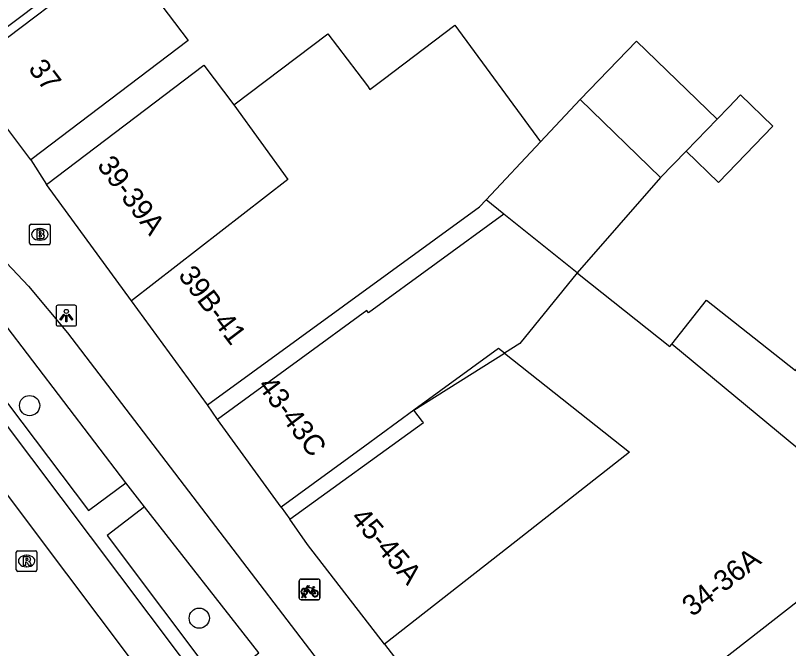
# Model space of a CAD drawing. Extents: x 161882 to 162509, y 381687 to 382379.
# Drawn here: x 162023.23 to 162060.59, y 382035.63 to 382066.22 of the extents above; entities that cross this region are included whole.
import ezdxf

# ---------------------------------------------------------------- set-up
doc = ezdxf.new("R2010")
doc.units = 0
for name, color, linetype in [('IMGEO_Boom', 7, 'Continuous'), ('IMGEO_Brandkraan', 7, 'Continuous'), ('IMGEO_Fietsenrek', 7, 'Continuous'), ('IMGEO_Fietspad_gesloten', 7, 'Continuous'), ('IMGEO_Lichtpunt', 7, 'Continuous'), ('IMGEO_Pand', 7, 'Continuous'), ('IMGEO_Pand_nummerreeks', 7, 'Continuous'), ('IMGEO_Rijbaan_lokaal_gesloten', 7, 'Continuous'), ('IMGEO_Rioolput', 7, 'Continuous'), ('IMGEO_Voetpad_open', 7, 'Continuous')]:
    doc.layers.add(name, color=color, linetype=linetype)

msp = doc.modelspace()

# ---------------------------------------------------------------- linework, layer by layer
at = {"layer": 'IMGEO_Boom'}
for centre in [(162023.912, 382047.368), (162032.11, 382037.095)]:
    msp.add_circle(centre, 0.489, dxfattribs=at)
at = {"layer": 'IMGEO_Brandkraan'}
for p, q in [((162023.908, 382055.218), (162023.908, 382056.07)), ((162023.983, 382056.144), (162024.835, 382056.144)), ((162024.909, 382056.07), (162024.909, 382055.218)), ((162024.396, 382055.924), (162024.421, 382055.924)), ((162024.419, 382055.364), (162024.394, 382055.364)), ((162024.835, 382055.144), (162023.983, 382055.144))]:
    msp.add_line(p, q, dxfattribs=at)
for points in [[(162023.908, 382055.218), (162023.908, 382056.07)], [(162023.983, 382056.144), (162024.835, 382056.144)], [(162024.909, 382056.07), (162024.909, 382055.218)], [(162024.256, 382055.844), (162024.256, 382055.444), (162024.469, 382055.444)], [(162024.487, 382055.844), (162024.256, 382055.844)], [(162024.435, 382055.763), (162024.381, 382055.763), (162024.381, 382055.687)], [(162024.381, 382055.687), (162024.434, 382055.687)], [(162024.443, 382055.611), (162024.381, 382055.611), (162024.381, 382055.53)], [(162024.381, 382055.53), (162024.443, 382055.53)], [(162024.835, 382055.144), (162023.983, 382055.144)]]:
    msp.add_lwpolyline(points, dxfattribs=at)
for centre, radius, start, end in [((162023.985, 382056.068), 0.0765, 91.552, 178.448), ((162023.985, 382056.068), 0.0765, 91.552, 178.448), ((162024.833, 382056.068), 0.0765, 1.552, 88.448), ((162024.833, 382056.068), 0.0765, 1.552, 88.448), ((162024.436, 382055.725), 0.0379, 267.8285, 90.9355), ((162024.444, 382055.57), 0.0404, 269.8759, 90.5077), ((162024.491, 382055.699), 0.145, 59.4692, 91.5367), ((162024.516, 382055.746), 0.0922, 285.5137, 58.1501), ((162024.521, 382055.554), 0.105, 301.3115, 78.989), ((162023.985, 382055.22), 0.0765, 181.552, 268.448), ((162023.985, 382055.22), 0.0765, 181.552, 268.448), ((162024.475, 382055.695), 0.251, 268.6676, 293.5347), ((162024.833, 382055.22), 0.0765, 271.552, 358.448), ((162024.833, 382055.22), 0.0765, 271.552, 358.448)]:
    msp.add_arc(centre, radius, start, end, dxfattribs=at)
for centre, major_axis, ratio, start_param, end_param in [((162024.395, 382055.644), (-0.387, 0.002), 0.722429, 4.712389, 7.853982), ((162024.42, 382055.644), (-0.39, 0.002), 0.717154, 1.570796, 4.712389)]:
    msp.add_ellipse(centre, major_axis=major_axis, ratio=ratio, start_param=start_param, end_param=end_param, dxfattribs=at)
at = {"layer": 'IMGEO_Fietsenrek'}
for p, q in [((162036.945, 382038.062), (162036.945, 382038.903)), ((162036.945, 382038.903), (162036.945, 382038.062)), ((162037.02, 382038.987), (162037.861, 382038.987)), ((162037.861, 382038.987), (162037.02, 382038.987)), ((162037.945, 382038.912), (162037.945, 382038.071)), ((162037.945, 382038.071), (162037.945, 382038.912)), ((162037.632, 382038.536), (162037.668, 382038.441)), ((162037.072, 382038.071), (162037.111, 382038.231)), ((162037.106, 382038.071), (162037.072, 382038.071)), ((162037.141, 382038.219), (162037.106, 382038.071)), ((162037.183, 382038.243), (162037.182, 382038.247)), ((162037.224, 382038.071), (162037.19, 382038.213)), ((162037.214, 382038.254), (162037.215, 382038.247)), ((162037.222, 382038.217), (162037.257, 382038.071)), ((162037.257, 382038.071), (162037.224, 382038.071)), ((162037.87, 382037.987), (162037.029, 382037.987)), ((162037.029, 382037.987), (162037.87, 382037.987))]:
    msp.add_line(p, q, dxfattribs=at)
for points in [[(162037.279, 382038.461), (162037.227, 382038.371), (162037.187, 382038.346), (162037.188, 382038.393), (162037.243, 382038.487)], [(162037.258, 382038.513), (162037.353, 382038.677), (162037.439, 382038.663), (162037.441, 382038.654), (162037.385, 382038.643), (162037.358, 382038.598), (162037.614, 382038.557)], [(162037.554, 382038.269), (162037.504, 382038.269), (162037.313, 382038.52), (162037.294, 382038.488)], [(162037.601, 382038.532), (162037.344, 382038.573), (162037.327, 382038.544), (162037.494, 382038.324), (162037.601, 382038.532)], [(162037.649, 382038.434), (162037.619, 382038.511), (162037.51, 382038.293), (162037.553, 382038.293)], [(162037.583, 382038.293), (162037.703, 382038.292), (162037.659, 382038.406)], [(162037.679, 382038.413), (162037.734, 382038.268), (162037.584, 382038.268)], [(162037.614, 382038.557), (162037.639, 382038.606), (162037.633, 382038.61), (162037.61, 382038.614), (162037.598, 382038.621), (162037.597, 382038.624), (162037.599, 382038.629), (162037.694, 382038.614), (162037.696, 382038.604), (162037.686, 382038.591), (162037.674, 382038.585), (162037.66, 382038.591), (162037.632, 382038.536)]]:
    msp.add_lwpolyline(points, dxfattribs=at)
for centre, radius, start, end in [((162037.023, 382038.909), 0.0779, 92.4484, 184.2845), ((162037.023, 382038.909), 0.0779, 92.4484, 184.2845), ((162037.867, 382038.909), 0.0779, 2.4484, 94.2845), ((162037.867, 382038.909), 0.0779, 2.4484, 94.2845), ((162037.185, 382038.372), 0.159, 62.6766, 242.1369), ((162037.185, 382038.372), 0.129, 63.3192, 238.903), ((162037.185, 382038.372), 0.129, 283.6043, 43.4302), ((162037.185, 382038.372), 0.159, 283.5766, 46.6042), ((162037.712, 382038.288), 0.159, 113.3408, 178.3217), ((162037.712, 382038.288), 0.159, 187.0065, 105.7708), ((162037.712, 382038.288), 0.129, 113.923, 177.9556), ((162037.712, 382038.288), 0.129, 188.6715, 104.5883), ((162037.023, 382038.065), 0.0779, 182.4484, 274.2845), ((162037.023, 382038.065), 0.0779, 182.4484, 274.2845), ((162037.165, 382038.243), 0.0499, 12.8025, 158.6934), ((162037.185, 382038.372), 0.159, 253.9967, 271.7867), ((162037.165, 382038.243), 0.0174, 12.8025, 163.4502), ((162037.185, 382038.372), 0.129, 253.415, 269.0204), ((162037.867, 382038.065), 0.0779, 272.4484, 4.2845), ((162037.867, 382038.065), 0.0779, 272.4484, 4.2845)]:
    msp.add_arc(centre, radius, start, end, dxfattribs=at)
at = {"layer": 'IMGEO_Fietspad_gesloten'}
for points in [[(162016.673, 382061.059), (162019.582, 382057.646), (162023.854, 382053.141), (162025.74, 382050.885), (162045.217, 382025.401)], [(162028.557, 382043.631), (162022.572, 382051.503), (162019.065, 382055.253)], [(162029.47, 382042.482), (162028.557, 382043.631)], [(162034.995, 382035.413), (162029.47, 382042.482)]]:
    msp.add_lwpolyline(points, dxfattribs=at)
at = {"layer": 'IMGEO_Lichtpunt'}
for p, q in [((162025.189, 382052.122), (162025.189, 382051.315)), ((162025.189, 382052.122), (162025.189, 382051.315)), ((162026.091, 382052.217), (162025.283, 382052.217)), ((162026.091, 382052.217), (162025.283, 382052.217)), ((162026.185, 382051.315), (162026.185, 382052.122)), ((162026.185, 382051.315), (162026.185, 382052.122)), ((162025.283, 382051.221), (162026.091, 382051.221)), ((162025.283, 382051.221), (162026.091, 382051.221))]:
    msp.add_line(p, q, dxfattribs=at)
for points in [[(162025.563, 382051.786), (162025.602, 382051.758), (162025.414, 382051.496), (162025.376, 382051.523), (162025.563, 382051.786)], [(162025.665, 382051.738), (162025.712, 382051.738), (162025.712, 382051.416), (162025.665, 382051.416), (162025.665, 382051.738)], [(162025.775, 382051.758), (162025.813, 382051.785), (162026, 382051.523), (162025.961, 382051.495), (162025.775, 382051.758)]]:
    msp.add_lwpolyline(points, dxfattribs=at)
msp.add_circle((162025.688, 382051.92), 0.0994, dxfattribs=at)
for centre, start, end in [((162025.283, 382052.122), 90, 180), ((162025.283, 382052.122), 90, 180), ((162026.091, 382052.122), 0, 90), ((162026.091, 382052.122), 0, 90), ((162025.283, 382051.315), 180, 270), ((162025.283, 382051.315), 180, 270), ((162026.091, 382051.315), 270, 0), ((162026.091, 382051.315), 270, 360)]:
    msp.add_arc(centre, 0.0946, start, end, dxfattribs=at)
at = {"layer": 'IMGEO_Pand'}
for points in [[(162020.16, 382072.446), (162023.392, 382074.893), (162027.615, 382069.316), (162024.472, 382066.904), (162020.48, 382063.901)], [(162020.714, 382063.56), (162028.32, 382069.318), (162031.58, 382065.013), (162023.974, 382059.255)], [(162033.784, 382061.907), (162038.323, 382065.344), (162039.723, 382063.495), (162040.236, 382062.818), (162040.362, 382062.651), (162041.002, 382063.136), (162044.47, 382065.763), (162048.598, 382060.112)], [(162050.518, 382062.162), (162053.249, 382064.983), (162057.141, 382061.214)], [(162024.729, 382058.062), (162032.335, 382063.82), (162033.784, 382061.907)], [(162023.974, 382059.255), (162020.714, 382063.56)], [(162057.141, 382061.214), (162057.697, 382061.788), (162058.275, 382062.386), (162059.839, 382060.872), (162057.201, 382058.147), (162055.637, 382059.661)], [(162048.598, 382060.112), (162050.518, 382062.162)], [(162054.41, 382058.393), (162050.518, 382062.162)], [(162033.784, 382061.907), (162036.394, 382058.303), (162028.842, 382052.427)], [(162057.141, 382061.214), (162055.637, 382059.661)], [(162045.973, 382057.316), (162048.598, 382060.112)], [(162055.637, 382059.661), (162054.41, 382058.393)], [(162054.41, 382058.393), (162050.377, 382053.786)], [(162028.842, 382052.427), (162024.729, 382058.062)], [(162032.512, 382047.399), (162045.655, 382056.977), (162045.973, 382057.316)], [(162046.829, 382056.621), (162045.973, 382057.316)], [(162046.829, 382056.621), (162040.282, 382051.849), (162040.21, 382051.965), (162037.028, 382049.643), (162032.989, 382046.695)], [(162050.377, 382053.786), (162046.829, 382056.621)], [(162050.377, 382053.786), (162047.606, 382050.366), (162046.855, 382049.898)], [(162050.377, 382053.786), (162050.472, 382053.71), (162054.858, 382050.224), (162054.951, 382050.341)], [(162032.512, 382047.399), (162028.842, 382052.427)], [(162054.951, 382050.341), (162056.627, 382052.463), (162060.925, 382049.066), (162062.728, 382051.348)], [(162046.855, 382049.898), (162046.566, 382050.126), (162042.481, 382047.145)], [(162065.624, 382041.496), (162054.951, 382050.341)], [(162046.855, 382049.898), (162052.91, 382045.111), (162047.42, 382040.818), (162041.057, 382035.842)], [(162042.481, 382047.145), (162046.855, 382049.898)], [(162042.481, 382047.145), (162040.112, 382045.416), (162036.073, 382042.468)], [(162036.489, 382041.876), (162042.945, 382046.551), (162042.901, 382046.607), (162042.481, 382047.145)], [(162036.073, 382042.468), (162032.989, 382046.695)], [(162041.057, 382035.842), (162037.344, 382040.661), (162036.489, 382041.876)], [(162065.624, 382041.496), (162047.564, 382027.394)], [(162041.057, 382035.842), (162043.769, 382032.321), (162044.539, 382032.914), (162045.722, 382031.377), (162044.952, 382030.784), (162047.564, 382027.394)]]:
    msp.add_lwpolyline(points, dxfattribs=at)
at = {"layer": 'IMGEO_Rijbaan_lokaal_gesloten'}
msp.add_lwpolyline([(162039.92, 382020.338), (162025.711, 382039.238), (162016.224, 382051.857)], dxfattribs=at)
at = {"layer": 'IMGEO_Rioolput'}
for p, q in [((162023.267, 382039.43), (162023.267, 382040.282)), ((162023.342, 382040.356), (162024.194, 382040.356)), ((162024.268, 382040.282), (162024.268, 382039.43)), ((162023.755, 382040.136), (162023.78, 382040.136)), ((162023.778, 382039.576), (162023.753, 382039.576)), ((162024.194, 382039.356), (162023.342, 382039.356))]:
    msp.add_line(p, q, dxfattribs=at)
for points in [[(162023.267, 382039.43), (162023.267, 382040.282)], [(162023.342, 382040.356), (162024.194, 382040.356)], [(162024.268, 382040.282), (162024.268, 382039.43)], [(162023.856, 382040.054), (162023.604, 382040.056), (162023.604, 382039.656)], [(162023.782, 382039.975), (162023.728, 382039.975), (162023.728, 382039.894)], [(162023.604, 382039.656), (162023.728, 382039.656), (162023.728, 382039.818), (162023.739, 382039.818)], [(162023.728, 382039.894), (162023.78, 382039.894)], [(162023.786, 382039.789), (162023.857, 382039.656), (162023.997, 382039.656), (162023.932, 382039.782)], [(162024.194, 382039.356), (162023.342, 382039.356)]]:
    msp.add_lwpolyline(points, dxfattribs=at)
for centre, radius, start, end in [((162023.344, 382040.28), 0.0765, 91.552, 178.448), ((162023.344, 382040.28), 0.0765, 91.552, 178.448), ((162024.192, 382040.28), 0.0765, 1.552, 88.448), ((162024.192, 382040.28), 0.0765, 1.552, 88.448), ((162023.764, 382040.083), 0.19, 274.7715, 282.9687), ((162023.788, 382039.879), 0.0964, 77.0061, 93.1865), ((162023.802, 382039.936), 0.0378, 276.6634, 79.6772), ((162023.855, 382039.944), 0.109, 350.3612, 89.416), ((162023.853, 382039.944), 0.112, 277.5842, 350.9817), ((162023.738, 382039.765), 0.0533, 26.0293, 88.6989), ((162023.837, 382039.729), 0.108, 29.5134, 73.7905), ((162023.344, 382039.432), 0.0765, 181.552, 268.448), ((162023.344, 382039.432), 0.0765, 181.552, 268.448), ((162024.192, 382039.432), 0.0765, 271.552, 358.448), ((162024.192, 382039.432), 0.0765, 271.552, 358.448)]:
    msp.add_arc(centre, radius, start, end, dxfattribs=at)
for centre, major_axis, ratio, start_param, end_param in [((162023.754, 382039.856), (-0.387, 0.002), 0.722429, 4.712389, 7.853982), ((162023.779, 382039.856), (-0.39, 0.002), 0.717154, 1.570796, 4.712389)]:
    msp.add_ellipse(centre, major_axis=major_axis, ratio=ratio, start_param=start_param, end_param=end_param, dxfattribs=at)
at = {"layer": 'IMGEO_Voetpad_open'}
for points in [[(162023.974, 382059.255), (162024.729, 382058.062)], [(162019.065, 382055.253), (162017.721, 382054.256), (162026.753, 382042.294), (162028.557, 382043.631)], [(162039.661, 382024.01), (162019.748, 382050.471), (162019.086, 382051.072), (162017.432, 382051.154)], [(162032.989, 382046.695), (162032.512, 382047.399)], [(162029.47, 382042.482), (162027.654, 382041.087), (162033.051, 382033.912), (162034.995, 382035.413)], [(162036.073, 382042.468), (162036.489, 382041.876)]]:
    msp.add_lwpolyline(points, dxfattribs=at)

# ---------------------------------------------------------------- texts
at = {"layer": 'IMGEO_Pand_nummerreeks'}
for s, rotation, p in [('37', 307.1291, (162023.812, 382063.643)), ('39-39A', 306.9505, (162027.136, 382058.971)), ('39B-41', 307.1446, (162031.059, 382053.656)), ('43-43C', 306.8238, (162034.898, 382048.321)), ('45-45A', 310.5136, (162039.383, 382041.914)), ('34-36A', 37.9814, (162055.941, 382037.132))]:
    msp.add_text(s, height=1, rotation=rotation, dxfattribs=at).set_placement(p)

doc.saveas('drawing.dxf')
